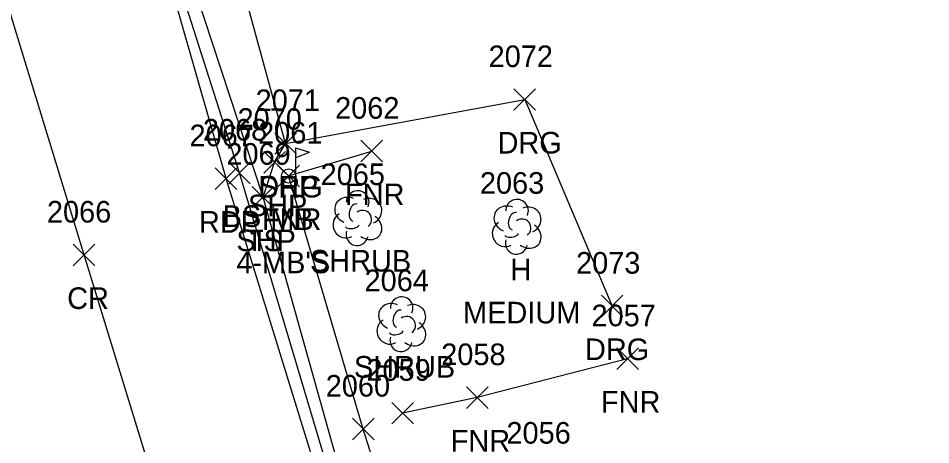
# Model space of a CAD drawing. Extents: x 1620157 to 1620595, y 115111 to 117885.
# Drawn here: x 1620251.8 to 1620336.2, y 115651.9 to 115691.4 of the extents above; entities that cross this region are included whole.
import ezdxf

# ---------------------------------------------------------------- set-up
doc = ezdxf.new("R2010")
doc.units = 0
for name, color, linetype in [('L_A', 7, 'Continuous'), ('L_C', 7, 'Continuous'), ('L_I', 7, 'Continuous'), ('L_TIC', 7, 'Continuous'), ('LELB', 7, 'Continuous'), ('LFNC', 7, 'Continuous'), ('LMB', 7, 'Continuous'), ('LSH', 7, 'Continuous'), ('LTD', 7, 'Continuous'), ('P_A', 7, 'Continuous'), ('P_I', 7, 'Continuous'), ('P_TIC', 7, 'Continuous'), ('PET', 7, 'Continuous'), ('PRC', 7, 'Continuous'), ('PSP', 7, 'Continuous'), ('R_A', 7, 'Continuous'), ('R_I', 7, 'Continuous'), ('R_TIC', 7, 'Continuous'), ('RDG', 7, 'Continuous'), ('S_I', 7, 'Continuous')]:
    doc.layers.add(name, color=color, linetype=linetype)

msp = doc.modelspace()

# ---------------------------------------------------------------- linework, layer by layer
at = {"layer": 'L_TIC'}
for points in [[(1620283.514, 115678.096), (1620285.514, 115680.096)], [(1620285.514, 115678.096), (1620283.514, 115680.096)], [(1620271.284, 115676.072), (1620273.284, 115678.072)], [(1620273.284, 115676.072), (1620271.284, 115678.072)], [(1620275.827, 115675.796), (1620277.827, 115677.796)], [(1620277.827, 115675.796), (1620275.827, 115677.796)], [(1620273.466, 115673.837), (1620275.466, 115675.837)], [(1620275.466, 115673.837), (1620273.466, 115675.837)], [(1620307.182, 115658.885), (1620309.182, 115660.885)], [(1620309.182, 115658.885), (1620307.182, 115660.885)], [(1620293.283, 115655.289), (1620295.283, 115657.289)], [(1620295.283, 115655.289), (1620293.283, 115657.289)], [(1620286.372, 115653.844), (1620288.372, 115655.844)], [(1620288.372, 115653.844), (1620286.372, 115655.844)], [(1620282.735, 115652.376), (1620284.735, 115654.376)], [(1620284.735, 115652.376), (1620282.735, 115654.376)], [(1620282.735, 115652.376), (1620284.735, 115654.376)], [(1620284.735, 115652.376), (1620282.735, 115654.376)]]:
    msp.add_lwpolyline(points, dxfattribs=at)
at = {"layer": 'LELB'}
for points in [[(1620284.85, 115634.911), (1620272.284, 115677.072), (1620264.785, 115700.582)], [(1620274.466, 115674.837), (1620266.718, 115698.512)], [(1620299.437, 115600.047), (1620289.918, 115633.869), (1620283.735, 115653.376)]]:
    msp.add_lwpolyline(points, dxfattribs=at)
at = {"layer": 'LFNC'}
for points in [[(1620283.735, 115653.376), (1620276.827, 115676.796), (1620284.514, 115679.096)], [(1620308.182, 115659.885), (1620294.283, 115656.289), (1620287.372, 115654.844)]]:
    msp.add_lwpolyline(points, dxfattribs=at)
at = {"layer": 'LMB'}
for p, q in [((1620277.477, 115679.396), (1620278.771, 115679.014)), ((1620277.483, 115676.804), (1620277.482, 115679.399)), ((1620277.482, 115678.497), (1620278.765, 115679.005)), ((1620276.827, 115676.796), (1620276.827, 115676.796))]:
    msp.add_line(p, q, dxfattribs=at)
msp.add_circle((1620276.827, 115676.796), 0.656, dxfattribs=at)
at = {"layer": 'LSH'}
for p, q in [((1620283.174, 115672.951), (1620283.174, 115672.951)), ((1620283.174, 115672.951), (1620283.174, 115672.951)), ((1620287.239, 115663.129), (1620287.239, 115663.129)), ((1620287.239, 115663.129), (1620287.239, 115663.129))]:
    msp.add_line(p, q, dxfattribs=at)
for centre in [(1620283.221, 115674.384), (1620287.285, 115664.563)]:
    msp.add_arc(centre, 1.047, 335.52715, 180.95627, dxfattribs=at)
for centre, major_axis, ratio, start_param, end_param in [((1620282.382, 115673.617), (1.21, -0.512), 0.895232, 1.570796, 4.712389), ((1620284.216, 115673.534), (-1.141, -0.483), 0.949671, 1.570796, 4.712389), ((1620282.966, 115673.409), (-0.208, -0.792), 0.645439, 3.141593, 6.283185), ((1620283.674, 115672.784), (-0.5, 0.667), 0.989748, 3.141593, 6.283185), ((1620282.091, 115672.242), (0.584, -1.042), 0.959034, 3.141593, 6.283185), ((1620284.174, 115672.117), (-1.09, 0.792), 0.841452, 1.570796, 4.712389), ((1620282.716, 115672.2), (-0.625, -0.083), 0.423636, 0, 3.141593), ((1620283.174, 115671.451), (0.265, 1.061), 0.942809, 1.570796, 4.712389), ((1620286.447, 115663.795), (1.21, -0.512), 0.895232, 1.570796, 4.712389), ((1620288.28, 115663.712), (-1.141, -0.483), 0.949671, 1.570796, 4.712389), ((1620287.03, 115663.587), (-0.208, -0.792), 0.645439, 3.141593, 6.283185), ((1620286.155, 115662.42), (0.584, -1.042), 0.959034, 3.141593, 6.283185), ((1620287.739, 115662.962), (-0.5, 0.667), 0.989748, 3.141593, 6.283185), ((1620288.239, 115662.296), (-1.09, 0.792), 0.841452, 1.570796, 4.712389), ((1620287.239, 115661.629), (0.265, 1.061), 0.942809, 1.570796, 4.712389), ((1620286.78, 115662.379), (-0.625, -0.083), 0.423636, 0, 3.141593)]:
    msp.add_ellipse(centre, major_axis=major_axis, ratio=ratio, start_param=start_param, end_param=end_param, dxfattribs=at)
at = {"layer": 'LTD'}
msp.add_line((1620297.909, 115672.15), (1620297.909, 115672.15), dxfattribs=at)
msp.add_line((1620297.909, 115672.15), (1620297.909, 115672.15), dxfattribs=at)
msp.add_arc((1620297.956, 115673.584), 1.047, 335.52715, 180.95627, dxfattribs=at)
for centre, major_axis, ratio, start_param, end_param in [((1620297.117, 115672.816), (1.21, -0.512), 0.895232, 1.570796, 4.712389), ((1620297.701, 115672.608), (-0.208, -0.792), 0.645439, 3.141593, 6.283185), ((1620298.951, 115672.733), (-1.141, -0.483), 0.949671, 1.570796, 4.712389), ((1620298.409, 115671.983), (-0.5, 0.667), 0.989748, 3.141593, 6.283185), ((1620296.826, 115671.441), (0.584, -1.042), 0.959034, 3.141593, 6.283185), ((1620298.909, 115671.317), (-1.09, 0.792), 0.841452, 1.570796, 4.712389), ((1620297.451, 115671.4), (-0.625, -0.083), 0.423636, 0, 3.141593), ((1620297.909, 115670.65), (0.265, 1.061), 0.942809, 1.570796, 4.712389)]:
    msp.add_ellipse(centre, major_axis=major_axis, ratio=ratio, start_param=start_param, end_param=end_param, dxfattribs=at)
at = {"layer": 'P_TIC'}
for points in [[(1620275.548, 115678.801), (1620277.548, 115680.801)], [(1620277.548, 115678.801), (1620275.548, 115680.801)], [(1620274.53, 115677.066), (1620276.53, 115679.066)], [(1620276.53, 115677.066), (1620274.53, 115679.066)], [(1620270.049, 115675.547), (1620272.049, 115677.547)], [(1620272.049, 115675.547), (1620270.049, 115677.547)], [(1620273.466, 115673.837), (1620275.466, 115675.837)], [(1620275.466, 115673.837), (1620273.466, 115675.837)], [(1620256.914, 115668.486), (1620258.914, 115670.486)], [(1620258.914, 115668.486), (1620256.914, 115670.486)]]:
    msp.add_lwpolyline(points, dxfattribs=at)
at = {"layer": 'PET'}
msp.add_lwpolyline([(1620336.223, 115456.795), (1620332.523, 115469.32), (1620324.589, 115500.95), (1620318.089, 115527.231), (1620313.062, 115541.759), (1620309.737, 115554.427), (1620302.898, 115574.327), (1620297.627, 115590.435), (1620296.31, 115595.422), (1620295.446, 115598.549), (1620285.025, 115631.411), (1620284.003, 115634.579), (1620271.049, 115676.547), (1620263.941, 115701.458), (1620257.196, 115724.05), (1620247.856, 115755.871), (1620237.557, 115791.502), (1620229.867, 115820.365), (1620222.522, 115845.456)], dxfattribs=at)
at = {"layer": 'PRC'}
msp.add_lwpolyline([(1620328.083, 115447.457), (1620322.143, 115466.609), (1620311.316, 115499.812), (1620303.781, 115522.909), (1620294.725, 115551.741), (1620279.311, 115600.233), (1620271.119, 115626.45), (1620257.914, 115669.486), (1620247.637, 115703.034), (1620242.452, 115719.653), (1620232.976, 115752.347), (1620223.662, 115784.044), (1620214.136, 115816.154), (1620207.469, 115841.181)], dxfattribs=at)
at = {"layer": 'PSP'}
msp.add_lwpolyline([(1620284.003, 115634.579), (1620284.85, 115634.911), (1620285.305, 115636.206), (1620274.466, 115674.837), (1620275.53, 115678.066), (1620276.548, 115679.801), (1620271.765, 115697.364), (1620266.718, 115698.512), (1620264.785, 115700.582), (1620263.941, 115701.458)], dxfattribs=at)
at = {"layer": 'R_TIC'}
for points in [[(1620297.665, 115682.873), (1620299.665, 115684.873)], [(1620299.665, 115682.873), (1620297.665, 115684.873)], [(1620275.548, 115678.801), (1620277.548, 115680.801)], [(1620277.548, 115678.801), (1620275.548, 115680.801)], [(1620305.754, 115663.756), (1620307.754, 115665.756)], [(1620307.754, 115663.756), (1620305.754, 115665.756)]]:
    msp.add_lwpolyline(points, dxfattribs=at)
at = {"layer": 'RDG'}
msp.add_lwpolyline([(1620276.548, 115679.801), (1620298.665, 115683.873), (1620306.754, 115664.756)], dxfattribs=at)

# ---------------------------------------------------------------- texts
at = {"layer": 'L_A'}
for s, p in [('FNR', (1620282.049, 115674.096)), ('BS', (1620270.725, 115672.072)), ('FNR', (1620274.363, 115671.796)), ('MB', (1620275.135, 115671.796)), ('TS', (1620272.876, 115669.837)), ('SHRUB', (1620278.804, 115667.951)), ('H', (1620297.342, 115667.15)), ('SHRUB', (1620282.869, 115658.129)), ('FNR', (1620305.718, 115654.885)), ('FNR', (1620291.818, 115651.289))]:
    msp.add_text(s, height=2, dxfattribs=at).set_placement(p)
at = {"layer": 'L_C'}
for s, p in [("4-MB'S", (1620271.993, 115667.796)), ('MEDIUM', (1620292.964, 115663.15))]:
    msp.add_text(s, height=2, dxfattribs=at).set_placement(p)
at = {"layer": 'L_I'}
for s, p in [('2062', (1620281.128, 115682.096)), ('2068', (1620268.898, 115680.072)), ('2061', (1620274.009, 115679.796)), ('2061', (1620274.009, 115679.796)), ('2069', (1620271.073, 115677.837)), ('2065', (1620279.788, 115675.951)), ('2063', (1620294.523, 115675.15)), ('2064', (1620283.853, 115666.129)), ('2057', (1620304.844, 115662.885)), ('2058', (1620290.944, 115659.289)), ('2059', (1620284.026, 115657.844)), ('2060', (1620280.263, 115656.376)), ('2060', (1620280.263, 115656.376))]:
    msp.add_text(s, height=2, dxfattribs=at).set_placement(p)
at = {"layer": 'P_A'}
for s, p in [('SHP', (1620274.084, 115674.801)), ('SHP', (1620273.066, 115673.066)), ('RDP', (1620268.537, 115671.547)), ('SHP', (1620272.002, 115669.837)), ('CR', (1620256.347, 115664.486))]:
    msp.add_text(s, height=2, dxfattribs=at).set_placement(p)
at = {"layer": 'P_I'}
for s, p in [('2071', (1620273.777, 115682.801)), ('2070', (1620272.105, 115681.066)), ('2067', (1620267.663, 115679.547)), ('2069', (1620271.073, 115677.837)), ('2066', (1620254.473, 115672.486))]:
    msp.add_text(s, height=2, dxfattribs=at).set_placement(p)
at = {"layer": 'R_A'}
for p in [(1620296.153, 115678.873), (1620274.036, 115674.801), (1620304.242, 115659.756)]:
    msp.add_text('DRG', height=2, dxfattribs=at).set_placement(p)
at = {"layer": 'R_I'}
for s, p in [('2072', (1620295.327, 115686.873)), ('2071', (1620273.777, 115682.801)), ('2073', (1620303.415, 115667.756))]:
    msp.add_text(s, height=2, dxfattribs=at).set_placement(p)
at = {"layer": 'S_I'}
msp.add_text('2056', height=2, dxfattribs=at).set_placement((1620296.976, 115652.022))

doc.saveas('drawing.dxf')
